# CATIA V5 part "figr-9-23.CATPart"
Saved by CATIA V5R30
Part number: Part2
Bounding box of the stored display mesh (mm): x -72 to 72, y -80 to 90, z -20 to 41.296
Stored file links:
  D:\PROJECTS\CATIA V56R 2020\Resources\Parts File\c09_catia_v5_6r2020_prt\figr-9-23.CATPart
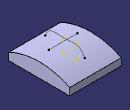
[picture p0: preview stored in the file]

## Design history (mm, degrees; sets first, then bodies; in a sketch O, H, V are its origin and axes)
Body1 (main body)
  Sketch1 on yz-plane, origin (0, 0, 0), H (0, 1, 0), V (0, 0, 1)
    arc A1 centre (5, -170) radius 190.0658 from (-80, 0) to (90, 0) cw
    point P2 (-80, 0)
    point P3 (0, 20)
    line L1 (-80, 0) -> (-80, -20)
    line L2 (-80, -20) -> (90, -20)
    line L3 (90, -20) -> (90, 0)
    coincidence: P2 H, A1 P3, P3 V
    vertical: L1 V, L3 V
    horizontal: L2 H
  Pad1: profile Sketch1, direction (1, 0, 0), length 72, mirrored extent
  Sketch2 on zx-plane, origin (0, 0, 0), H (-1, 0, 0), V (0, 0, 1)
    line L1 (-40, 30) -> (40, 30)
    horizontal: L1 H
  Sketch3 on yz-plane, origin (0, 0, 0), H (0, 1, 0), V (0, 0, 1)
    spline S1 through (60, 20) (40, 40) (10, 40) (-10, 40) (-30, 40) (-50, 20)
